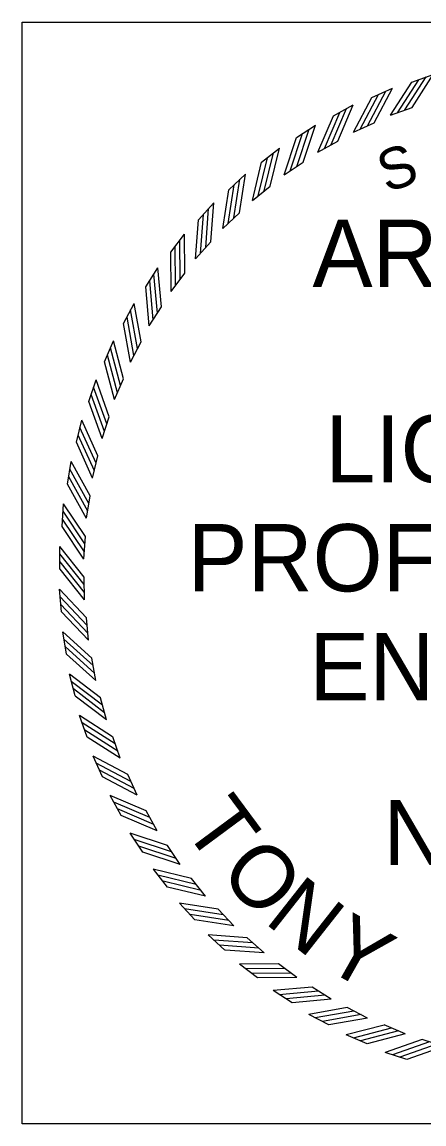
# Model space of a CAD drawing. Extents: x 0 to 1228740, y 0 to 152440.
# Drawn here: x 39.633 to 40.635, y 22.633 to 25.383 of the extents above; entities that cross this region are included whole.
import ezdxf

# ---------------------------------------------------------------- set-up
doc = ezdxf.new("R2010")
doc.units = 0
doc.layers.add('R_No Plot', color=7, linetype='Continuous')
doc.layers.add('STAMP_TNC', color=7, linetype='Continuous')

msp = doc.modelspace()

# ---------------------------------------------------------------- linework, layer by layer
at = {"layer": 'R_No Plot'}
msp.add_lwpolyline([(39.6327, 25.3826), (42.3827, 25.3826), (42.3827, 22.6326), (39.6327, 22.6326)], close=True, dxfattribs=at)
at = {"layer": 'STAMP_TNC'}
for p, q in [((40.6045, 25.2329), (40.6578, 25.2517)), ((40.505, 25.1946), (40.5566, 25.2178)), ((40.409, 25.1483), (40.4585, 25.1757)), ((40.5518, 25.1504), (40.6053, 25.1693)), ((40.3172, 25.0942), (40.3642, 25.1256)), ((40.4593, 25.1081), (40.511, 25.1314)), ((40.3706, 25.0583), (40.4202, 25.0857)), ((40.2301, 25.0327), (40.2744, 25.0679)), ((40.2863, 25.0013), (40.3335, 25.0328)), ((40.1484, 24.9642), (40.1897, 25.0029)), ((40.207, 24.9376), (40.2514, 24.9728)), ((40.0726, 24.8892), (40.1106, 24.9312)), ((40.1333, 24.8676), (40.1746, 24.9063)), ((40.0033, 24.8083), (40.0377, 24.8532)), ((40.0655, 24.7916), (40.1036, 24.8337)), ((39.941, 24.7218), (39.9714, 24.7694)), ((40.0043, 24.7104), (40.0387, 24.7555)), ((39.8859, 24.6305), (39.9124, 24.6805)), ((39.95, 24.6244), (39.9806, 24.6721)), ((39.8386, 24.535), (39.8609, 24.587)), ((39.903, 24.5342), (39.9295, 24.5843)), ((39.7994, 24.4359), (39.8172, 24.4895)), ((39.8636, 24.4404), (39.8859, 24.4925)), ((39.8321, 24.3437), (39.85, 24.3974)), ((39.7684, 24.3339), (39.7818, 24.3888)), ((39.746, 24.2297), (39.7548, 24.2855)), ((39.8086, 24.2447), (39.822, 24.2997)), ((39.7935, 24.1441), (39.8023, 24.2001)), ((39.7323, 24.124), (39.7364, 24.1804)), ((39.7866, 24.0426), (39.7908, 24.0991)), ((39.7273, 24.0175), (39.7268, 24.074)), ((39.7882, 23.9409), (39.7877, 23.9975)), ((39.7312, 23.9109), (39.726, 23.9673)), ((39.7982, 23.8396), (39.793, 23.8961)), ((39.7438, 23.8051), (39.734, 23.8608)), ((39.8165, 23.7396), (39.8067, 23.7954)), ((39.7652, 23.7007), (39.7508, 23.7554)), ((39.843, 23.6413), (39.8286, 23.6962)), ((39.7951, 23.5983), (39.7762, 23.6517)), ((39.8775, 23.5457), (39.8587, 23.5991)), ((39.8333, 23.4988), (39.8101, 23.5504)), ((39.9199, 23.4531), (39.8966, 23.5048)), ((39.8797, 23.4028), (39.8523, 23.4523)), ((39.9697, 23.3644), (39.9422, 23.414)), ((39.9338, 23.311), (39.9024, 23.358)), ((40.0266, 23.2802), (39.9952, 23.3273)), ((39.9953, 23.2239), (39.9601, 23.2682)), ((40.0904, 23.2009), (40.0551, 23.2453)), ((40.0637, 23.1422), (40.025, 23.1835)), ((40.1604, 23.1271), (40.1216, 23.1684)), ((40.1387, 23.0665), (40.0968, 23.1044)), ((40.2363, 23.0594), (40.1943, 23.0974)), ((40.2197, 22.9972), (40.1748, 23.0315)), ((40.3176, 22.9981), (40.2725, 23.0325)), ((40.3061, 22.9348), (40.2585, 22.9653)), ((40.4036, 22.9438), (40.3559, 22.9744)), ((40.4938, 22.8968), (40.4437, 22.9233)), ((40.3974, 22.8797), (40.3475, 22.9062)), ((40.493, 22.8324), (40.441, 22.8547)), ((40.5876, 22.8574), (40.5355, 22.8797)), ((40.6843, 22.8259), (40.6305, 22.8438)), ((40.5921, 22.7932), (40.5384, 22.8111))]:
    msp.add_line(p, q, dxfattribs=at)
for points in [[(40.5874, 25.1632), (40.6401, 25.2457)], [(40.6052, 25.1693), (40.6579, 25.2518)], [(40.5109, 25.1314), (40.5566, 25.2179)], [(40.5518, 25.1503), (40.6045, 25.2328)], [(40.569, 25.1563), (40.6217, 25.2387)], [(40.4593, 25.108), (40.505, 25.1946)], [(40.4759, 25.1153), (40.5216, 25.2019)], [(40.4937, 25.1238), (40.5394, 25.2103)], [(40.4036, 25.0768), (40.442, 25.1668)], [(40.4201, 25.0857), (40.4585, 25.1757)], [(40.3706, 25.0582), (40.409, 25.1482)], [(40.3866, 25.0669), (40.425, 25.1569)], [(40.3176, 25.0225), (40.3485, 25.1153)], [(40.3334, 25.0328), (40.3642, 25.1256)], [(40.2863, 25.0013), (40.3171, 25.0941)], [(40.3015, 25.0112), (40.3324, 25.1041)], [(40.2365, 24.9613), (40.2596, 25.0564)], [(40.2514, 24.9728), (40.2744, 25.0679)], [(40.207, 24.9375), (40.2301, 25.0326)], [(40.2214, 24.9487), (40.2444, 25.0438)], [(40.1745, 24.9063), (40.1897, 25.003)], [(40.1467, 24.8798), (40.1618, 24.9765)], [(40.1607, 24.8936), (40.1758, 24.9902)], [(40.1333, 24.8675), (40.1484, 24.9641)], [(40.0907, 24.8198), (40.0978, 24.9174)], [(40.1035, 24.8337), (40.1106, 24.9313)], [(40.0655, 24.7916), (40.0726, 24.8892)], [(40.0779, 24.805), (40.085, 24.9025)], [(40.0271, 24.7406), (40.0261, 24.8384)], [(40.0387, 24.7554), (40.0377, 24.8533)], [(40.0043, 24.7103), (40.0033, 24.8082)], [(40.0155, 24.7247), (40.0145, 24.8225)], [(39.9702, 24.6563), (39.9611, 24.7537)], [(39.9805, 24.6721), (39.9714, 24.7695)], [(39.96, 24.6395), (39.9509, 24.737)], [(39.95, 24.6243), (39.941, 24.7217)], [(39.9295, 24.5842), (39.9124, 24.6806)], [(39.9117, 24.5501), (39.8946, 24.6464)], [(39.9205, 24.5677), (39.9034, 24.664)], [(39.903, 24.5341), (39.8859, 24.6304)], [(39.8858, 24.4925), (39.8608, 24.5871)], [(39.8783, 24.4752), (39.8533, 24.5698)], [(39.8636, 24.4403), (39.8386, 24.5349)], [(39.8709, 24.457), (39.8459, 24.5516)], [(39.8499, 24.3974), (39.8172, 24.4896)], [(39.838, 24.3608), (39.8053, 24.453)], [(39.8438, 24.3796), (39.8111, 24.4718)], [(39.8321, 24.3436), (39.7994, 24.4358)], [(39.8174, 24.2814), (39.7771, 24.3706)], [(39.822, 24.2997), (39.7818, 24.3889)], [(39.8131, 24.2622), (39.7729, 24.3514)], [(39.8087, 24.2446), (39.7685, 24.3338)], [(39.8022, 24.2), (39.7548, 24.2856)], [(39.7991, 24.1814), (39.7517, 24.267)], [(39.7935, 24.144), (39.7461, 24.2296)], [(39.7965, 24.162), (39.7491, 24.2475)], [(39.7908, 24.099), (39.7364, 24.1804)], [(39.7892, 24.0803), (39.7348, 24.1616)], [(39.7867, 24.0425), (39.7323, 24.1239)], [(39.7882, 24.0606), (39.7338, 24.142)], [(39.7877, 23.9975), (39.7268, 24.0741)], [(39.7877, 23.9786), (39.7268, 24.0552)], [(39.7883, 23.959), (39.7274, 24.0356)], [(39.7883, 23.9408), (39.7274, 24.0174)], [(39.793, 23.896), (39.726, 23.9673)], [(39.7945, 23.8772), (39.7275, 23.9485)], [(39.7968, 23.8577), (39.7298, 23.929)], [(39.7983, 23.8396), (39.7313, 23.9109)], [(39.8066, 23.7953), (39.734, 23.8608)], [(39.8097, 23.7767), (39.7371, 23.8423)], [(39.8136, 23.7575), (39.7409, 23.823)], [(39.8166, 23.7395), (39.7439, 23.805)], [(39.8286, 23.6961), (39.7508, 23.7554)], [(39.8332, 23.6778), (39.7554, 23.7371)], [(39.8386, 23.6589), (39.7608, 23.7182)], [(39.8431, 23.6413), (39.7653, 23.7006)], [(39.8586, 23.599), (39.7762, 23.6517)], [(39.8648, 23.5812), (39.7823, 23.6339)], [(39.8717, 23.5628), (39.7893, 23.6155)], [(39.8776, 23.5456), (39.7952, 23.5983)], [(39.8966, 23.5048), (39.8101, 23.5504)], [(39.9042, 23.4875), (39.8176, 23.5332)], [(39.9126, 23.4698), (39.8261, 23.5155)], [(39.9199, 23.4531), (39.8334, 23.4988)], [(39.9422, 23.414), (39.8522, 23.4523)], [(39.9512, 23.3974), (39.8612, 23.4358)], [(39.9611, 23.3804), (39.8711, 23.4188)], [(39.9697, 23.3644), (39.8797, 23.4028)], [(39.9952, 23.3272), (39.9023, 23.3581)], [(40.0055, 23.3115), (39.9126, 23.3423)], [(40.0168, 23.2954), (39.9239, 23.3262)], [(40.0267, 23.2801), (39.9338, 23.3109)], [(40.0551, 23.2452), (39.96, 23.2682)], [(40.0667, 23.2303), (39.9716, 23.2534)], [(40.0793, 23.2152), (39.9842, 23.2383)], [(40.0904, 23.2008), (39.9953, 23.2239)], [(40.1217, 23.1684), (40.025, 23.1835)], [(40.1344, 23.1545), (40.0377, 23.1696)], [(40.1482, 23.1405), (40.0515, 23.1556)], [(40.1605, 23.1271), (40.0638, 23.1422)], [(40.1943, 23.0973), (40.0967, 23.1044)], [(40.2082, 23.0845), (40.1106, 23.0916)], [(40.223, 23.0717), (40.1254, 23.0788)], [(40.2364, 23.0594), (40.1388, 23.0665)], [(40.2725, 23.0325), (40.1747, 23.0315)], [(40.2874, 23.0209), (40.1896, 23.0199)], [(40.3033, 23.0093), (40.2054, 23.0083)], [(40.3177, 22.9981), (40.2198, 22.9972)], [(40.3559, 22.9743), (40.2585, 22.9653)], [(40.3717, 22.964), (40.2742, 22.955)], [(40.3884, 22.9538), (40.291, 22.9447)], [(40.4037, 22.9438), (40.3062, 22.9348)], [(40.4437, 22.9233), (40.3474, 22.9062)], [(40.4603, 22.9143), (40.364, 22.8972)], [(40.4779, 22.9055), (40.3815, 22.8884)], [(40.4939, 22.8968), (40.3975, 22.8798)], [(40.5355, 22.8796), (40.4409, 22.8547)], [(40.5528, 22.8721), (40.4582, 22.8471)], [(40.571, 22.8648), (40.4764, 22.8398)], [(40.5877, 22.8574), (40.4931, 22.8325)], [(40.6306, 22.8437), (40.5384, 22.811)], [(40.6484, 22.8376), (40.5562, 22.8049)], [(40.6672, 22.8318), (40.575, 22.7991)], [(40.6844, 22.8259), (40.5922, 22.7932)]]:
    msp.add_lwpolyline(points, dxfattribs=at)

# ---------------------------------------------------------------- texts
for s, height, rotation, p in [('S', 0.1029, 19.7726, (40.5419, 24.9556)), ('T', 0.1562, 306.5026, (40.0312, 23.3739)), ('O', 0.1562, 313.7811, (40.1199, 23.2541)), ('N', 0.1562, 321.7876, (40.234, 23.1365)), ('Y', 0.1562, 330.5218, (40.3759, 23.0278))]:
    msp.add_text(s, height=height, rotation=rotation, dxfattribs=at).set_placement(p)
for s, height, p in [('ARKANSAS', 0.16791, (40.357, 24.7216)), ('LICENSED', 0.16791, (40.389, 24.2336)), ('PROFESSIONAL', 0.167907, (40.0452, 23.9618)), ('ENGINEER', 0.16791, (40.349, 23.6899)), ('No.12370', 0.16191, (40.5342, 23.2789))]:
    msp.add_text(s, height=height, dxfattribs=at).set_placement(p)

doc.saveas('drawing.dxf')
